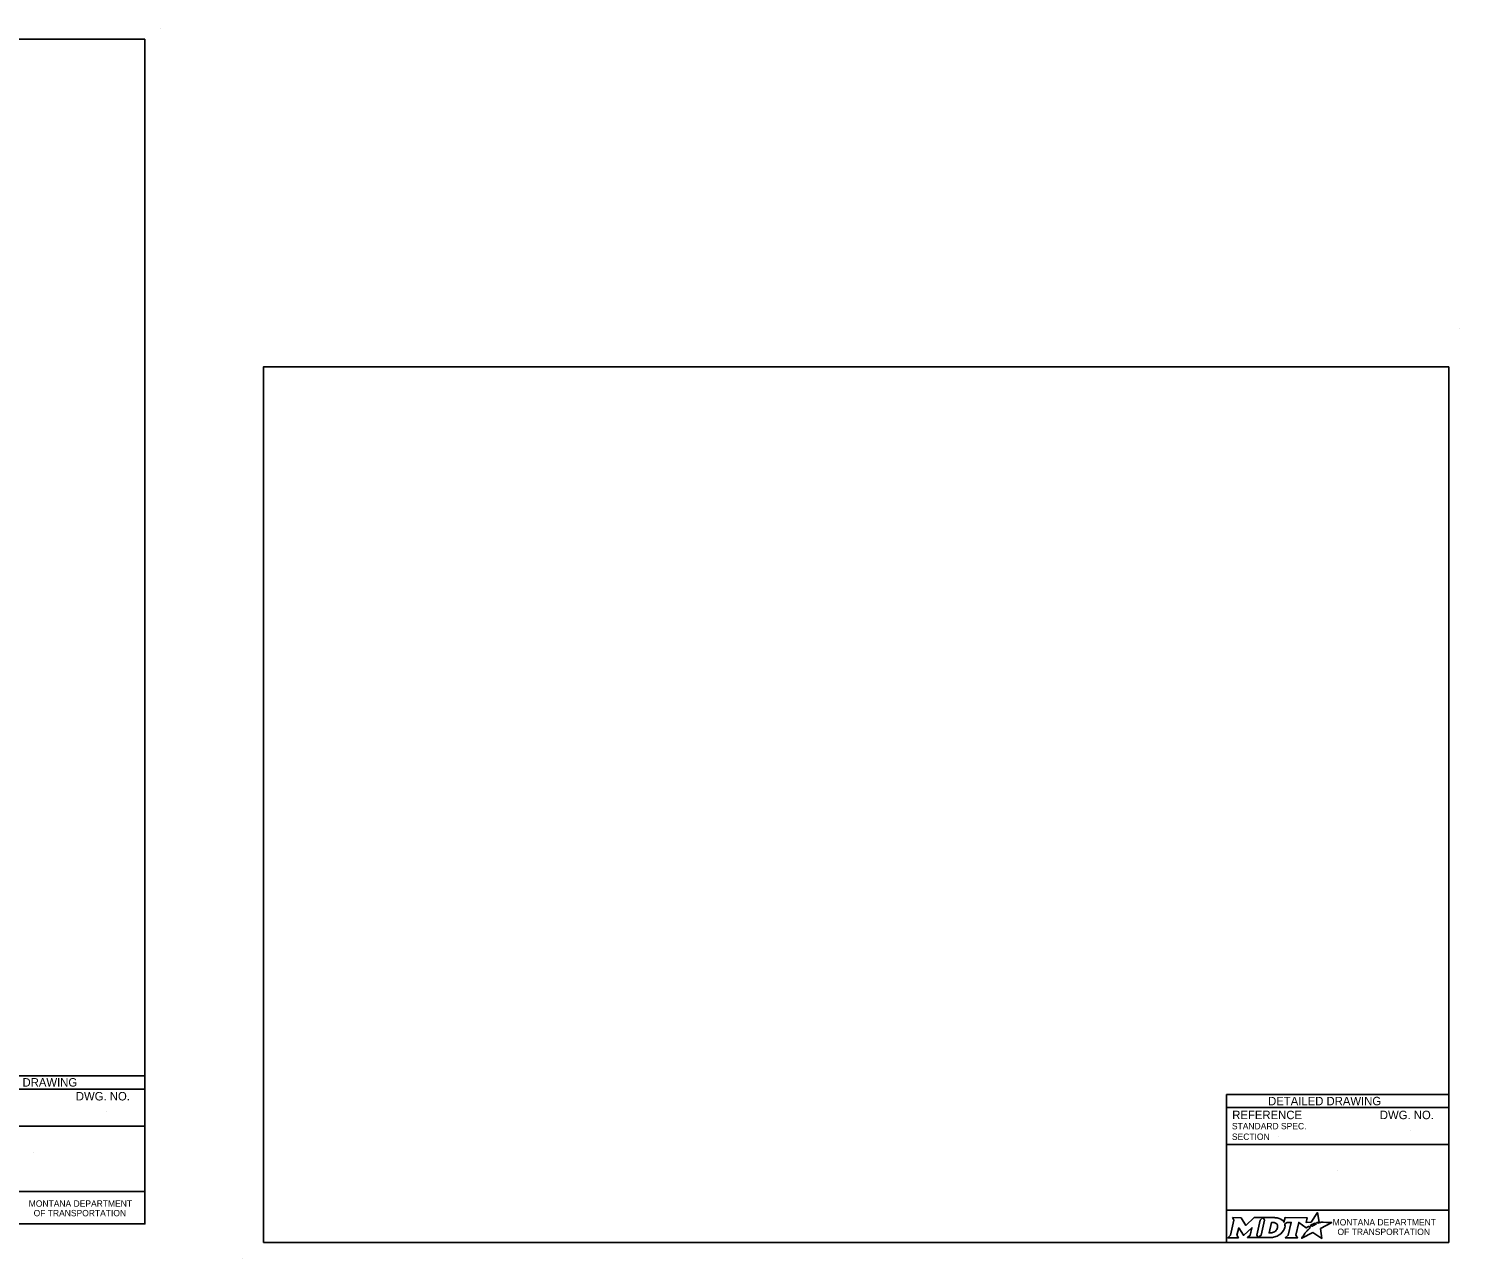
# Model space of a CAD drawing. Extents: x 49991.4 to 50021, y 49987.6 to 50011.4.
# Drawn here: x 50007.52 to 50021.04, y 49999.74 to 50011.36 of the extents above; entities that cross this region are included whole.
import ezdxf

# ---------------------------------------------------------------- set-up
doc = ezdxf.new("R2010")
doc.units = 0
for name, color, linetype in [('Default', 7, 'Continuous'), ('Level 1', 7, 'Continuous'), ('Level 2', 7, 'Continuous'), ('Level 4', 7, 'Continuous')]:
    doc.layers.add(name, color=color, linetype=linetype)

msp = doc.modelspace()

# ---------------------------------------------------------------- linework, layer by layer
at = {"layer": 'Default'}
for points in [[(50018.893, 50000.121), (50018.907, 50000.097), (50018.874, 49999.954), (50018.848, 49999.931), (50018.95, 49999.931), (50018.936, 49999.954), (50018.952, 50000.024), (50018.996, 49999.955), (50019.002, 49999.955), (50019.077, 50000.025), (50019.06, 49999.954), (50019.035, 49999.932), (50019.137, 49999.932), (50019.123, 49999.955), (50019.156, 50000.097)], [(50019.156, 50000.097), (50019.182, 50000.121), (50019.099, 50000.121), (50019.02, 50000.048), (50018.975, 50000.12), (50018.893, 50000.121)], [(50019.295, 50000.121), (50019.182, 50000.121), (50019.196, 50000.098), (50019.163, 49999.954), (50019.137, 49999.932), (50019.248, 49999.932)], [(50019.319, 50000.034), (50019.318, 50000.026), (50019.315, 50000.017), (50019.311, 50000.008), (50019.305, 50000.001), (50019.299, 49999.994), (50019.291, 49999.988), (50019.282, 49999.983), (50019.273, 49999.979), (50019.264, 49999.977), (50019.255, 49999.976), (50019.239, 49999.976), (50019.263, 50000.076), (50019.279, 50000.076), (50019.286, 50000.075), (50019.294, 50000.073), (50019.301, 50000.07), (50019.307, 50000.066), (50019.311, 50000.061), (50019.315, 50000.055), (50019.318, 50000.049), (50019.319, 50000.042), (50019.32, 50000.038), (50019.319, 50000.034)], [(50019.7, 50000.068), (50019.69, 50000.074), (50019.702, 50000.076), (50019.713, 50000.078), (50019.696, 50000.168), (50019.636, 50000.077), (50019.589, 50000.076), (50019.599, 50000.12), (50019.39, 50000.121), (50019.38, 50000.078), (50019.374, 50000.086)], [(50019.387, 50000.062), (50019.411, 50000.075), (50019.448, 50000.075), (50019.42, 49999.954), (50019.392, 49999.931), (50019.508, 49999.931), (50019.491, 49999.954), (50019.52, 50000.075), (50019.591, 50000.023), (50019.612, 50000.038), (50019.632, 50000.027)], [(50019.576, 49999.971), (50019.561, 49999.947), (50019.556, 49999.939), (50019.55, 49999.931), (50019.548, 49999.926), (50019.653, 49999.979), (50019.737, 49999.924), (50019.724, 50000.017), (50019.831, 50000.075), (50019.782, 50000.076), (50019.751, 50000.077), (50019.731, 50000.077), (50019.724, 50000.075), (50019.719, 50000.074), (50019.711, 50000.072), (50019.7, 50000.068)], [(50019.65, 50000.04), (50019.648, 50000.039), (50019.629, 50000.048), (50019.639, 50000.054), (50019.644, 50000.056), (50019.652, 50000.06), (50019.658, 50000.063), (50019.666, 50000.066), (50019.673, 50000.068), (50019.685, 50000.061), (50019.681, 50000.059), (50019.676, 50000.056), (50019.672, 50000.054), (50019.667, 50000.051), (50019.665, 50000.05), (50019.662, 50000.049), (50019.66, 50000.047), (50019.658, 50000.046), (50019.655, 50000.044), (50019.652, 50000.042), (50019.65, 50000.04)], [(50019.293, 49999.939), (50019.302, 49999.942), (50019.315, 49999.947), (50019.335, 49999.958)], [(50019.59, 49999.987), (50019.59, 49999.987)]]:
    msp.add_lwpolyline(points, dxfattribs=at)
for centre, radius, start, end in [((50019.319, 50000.042), 0.0709, 339.5329, 15.8582), ((50019.274, 50000.059), 0.118, 300.9103, 339.1383)]:
    msp.add_arc(centre, radius, start, end, dxfattribs=at)
for centre, major_axis, ratio, start_param, end_param in [((50019.293, 50000.073), (0.0834, -0.0037), 0.568097, 0.61298, 1.570796), ((50019.349, 50000.081), (0.0361, -0.0295), 0.469099, 1.225588, 1.570796), ((50019.248, 50000.08), (0, 0.148), 0.987302, 3.139398, 3.456847), ((50019.583, 49999.979), (-0.00694, -0.00806), 0.008222, 0, 3.137361), ((50019.6, 49999.997), (-0.0098, -0.0102), 0.016458, 3.141593, 6.279097), ((50019.621, 50000.017), (-0.0112, -0.0097), 0.021651, 3.157348, 6.283185)]:
    msp.add_ellipse(centre, major_axis=major_axis, ratio=ratio, start_param=start_param, end_param=end_param, dxfattribs=at)
at = {"layer": 'Level 1'}
for p, q in [((50008.765, 50011.363), (50008.765, 50011.363)), ((50021.038, 50008.524), (50021.038, 50008.524)), ((50009.537, 49999.736), (50009.537, 49999.736))]:
    msp.add_line(p, q, dxfattribs=at)
for points in [[(50008.615, 50011.263), (50000.336, 50011.263), (50000.336, 50000.062), (50008.615, 50000.062)], [(50020.938, 50008.165), (50009.737, 50008.165), (50009.737, 49999.886), (50020.938, 49999.886)]]:
    msp.add_lwpolyline(points, close=True, dxfattribs=at)
at = {"layer": 'Level 2'}
for p, q in [((50008.615, 50001.462), (50006.515, 50001.462)), ((50008.615, 50001.337), (50006.515, 50001.337)), ((50008.251, 50001.122), (50008.251, 50001.122)), ((50008.615, 50000.987), (50006.515, 50000.987)), ((50007.565, 50000.738), (50007.565, 50000.738)), ((50008.615, 50000.369), (50006.515, 50000.369))]:
    msp.add_line(p, q, dxfattribs=at)
at = {"layer": 'Level 4'}
for p, q in [((50020.938, 50001.286), (50018.838, 50001.286)), ((50018.838, 50001.286), (50018.838, 49999.886)), ((50020.938, 50001.161), (50018.838, 50001.161)), ((50019.332, 50000.886), (50019.332, 50000.886)), ((50020.574, 50000.946), (50020.574, 50000.946)), ((50020.938, 50000.811), (50018.838, 50000.811)), ((50019.888, 50000.562), (50019.888, 50000.562)), ((50020.938, 50000.193), (50018.838, 50000.193))]:
    msp.add_line(p, q, dxfattribs=at)

# ---------------------------------------------------------------- texts
at = {"layer": 'Default'}
for s, p in [('MONTANA DEPARTMENT', (50019.84, 50000.047)), ('OF TRANSPORTATION', (50019.886, 49999.957))]:
    msp.add_text(s, height=0.06, rotation=360, dxfattribs=at).set_placement(p)
at = {"layer": 'Level 2'}
for s, height, p in [('DETAILED DRAWING', 0.0799, (50006.906, 50001.36)), ('DWG. NO.', 0.08, (50007.962, 50001.229))]:
    msp.add_text(s, height=height, dxfattribs=at).set_placement(p)
for s, p in [('MONTANA DEPARTMENT', (50007.517, 50000.224)), ('OF TRANSPORTATION', (50007.563, 50000.134))]:
    msp.add_text(s, height=0.06, rotation=360, dxfattribs=at).set_placement(p)
at = {"layer": 'Level 4'}
for s, height, p in [('REFERENCE', 0.08, (50018.891, 50001.052)), ('DETAILED DRAWING', 0.0799, (50019.23, 50001.183)), ('DWG. NO.', 0.08, (50020.286, 50001.052)), ('STANDARD SPEC.', 0.06, (50018.888, 50000.956)), ('SECTION', 0.06, (50018.888, 50000.856))]:
    msp.add_text(s, height=height, dxfattribs=at).set_placement(p)

doc.saveas('drawing.dxf')
